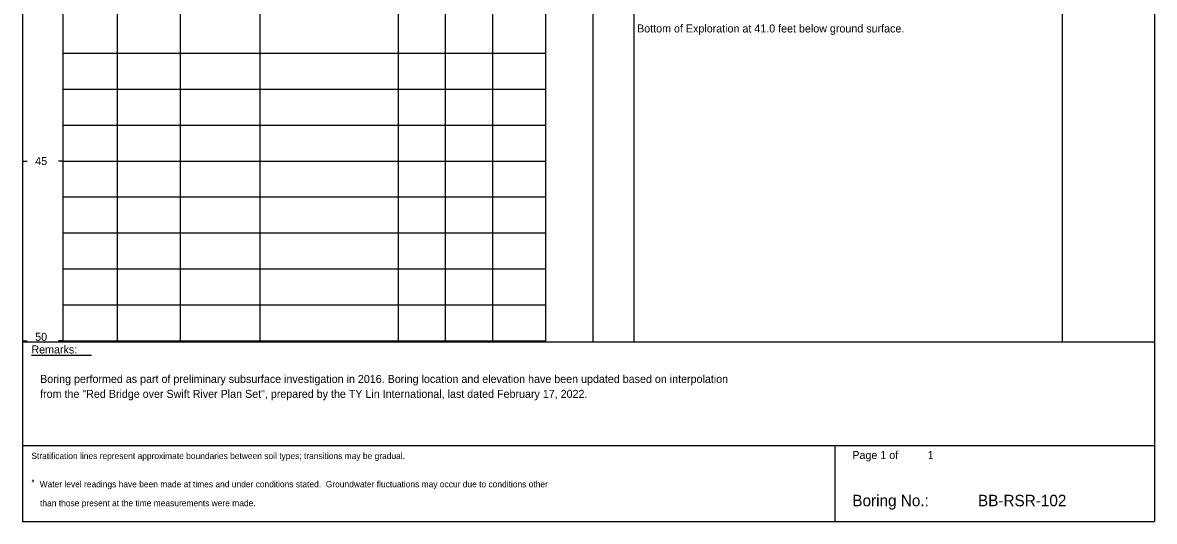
# Model space of a CAD drawing. Extents: x 9422 to 9552, y 6780 to 6860.
# Drawn here: x 9460.28 to 9491.78, y 6791.99 to 6805.86 of the extents above; entities that cross this region are included whole.
import ezdxf

# ---------------------------------------------------------------- set-up
doc = ezdxf.new("R2010")
doc.units = 0
doc.layers.add('7', color=7, linetype='Continuous')

msp = doc.modelspace()

# ---------------------------------------------------------------- linework, layer by layer
at = {"layer": '7'}
msp.add_line((9460.526, 6796.614), (9462.203, 6796.614), dxfattribs=at)
for points in [[(9460.282, 6822.038), (9460.282, 6791.992)], [(9461.4, 6822.038), (9461.4, 6796.983)], [(9462.909, 6822.038), (9462.909, 6796.983)], [(9464.665, 6822.038), (9464.665, 6796.983)], [(9466.879, 6822.038), (9466.879, 6796.983)], [(9470.734, 6822.038), (9470.734, 6796.983)], [(9472.046, 6822.038), (9472.046, 6796.983)], [(9473.359, 6822.038), (9473.359, 6796.983)], [(9474.835, 6822.038), (9474.835, 6796.983)], [(9476.148, 6822.038), (9476.148, 6796.983)], [(9477.296, 6822.038), (9477.296, 6796.983)], [(9489.214, 6822.038), (9489.214, 6796.983)], [(9491.778, 6822.038), (9491.778, 6791.992)], [(9461.4, 6805.011), (9462.909, 6805.011)], [(9462.909, 6805.011), (9464.665, 6805.011)], [(9464.665, 6805.011), (9466.879, 6805.011)], [(9466.879, 6805.011), (9470.734, 6805.011)], [(9470.734, 6805.011), (9472.046, 6805.011)], [(9472.046, 6805.011), (9473.359, 6805.011)], [(9473.359, 6805.011), (9474.835, 6805.011)], [(9461.4, 6804.011), (9462.909, 6804.011)], [(9462.909, 6804.011), (9464.665, 6804.011)], [(9464.665, 6804.011), (9466.879, 6804.011)], [(9466.879, 6804.011), (9470.734, 6804.011)], [(9470.734, 6804.011), (9472.046, 6804.011)], [(9472.046, 6804.011), (9473.359, 6804.011)], [(9473.359, 6804.011), (9474.835, 6804.011)], [(9461.4, 6803.011), (9462.909, 6803.011)], [(9462.909, 6803.011), (9464.665, 6803.011)], [(9464.665, 6803.011), (9466.879, 6803.011)], [(9466.879, 6803.011), (9470.734, 6803.011)], [(9470.734, 6803.011), (9472.046, 6803.011)], [(9472.046, 6803.011), (9473.359, 6803.011)], [(9473.359, 6803.011), (9474.835, 6803.011)], [(9460.282, 6802.011), (9460.404, 6802.011)], [(9461.4, 6802.011), (9461.279, 6802.011)], [(9461.4, 6802.011), (9462.909, 6802.011)], [(9462.909, 6802.011), (9464.665, 6802.011)], [(9464.665, 6802.011), (9466.879, 6802.011)], [(9466.879, 6802.011), (9470.734, 6802.011)], [(9470.734, 6802.011), (9472.046, 6802.011)], [(9472.046, 6802.011), (9473.359, 6802.011)], [(9473.359, 6802.011), (9474.835, 6802.011)], [(9461.4, 6801.011), (9462.909, 6801.011)], [(9462.909, 6801.011), (9464.665, 6801.011)], [(9464.665, 6801.011), (9466.879, 6801.011)], [(9466.879, 6801.011), (9470.734, 6801.011)], [(9470.734, 6801.011), (9472.046, 6801.011)], [(9472.046, 6801.011), (9473.359, 6801.011)], [(9473.359, 6801.011), (9474.835, 6801.011)], [(9461.4, 6800.011), (9462.909, 6800.011)], [(9462.909, 6800.011), (9464.665, 6800.011)], [(9464.665, 6800.011), (9466.879, 6800.011)], [(9466.879, 6800.011), (9470.734, 6800.011)], [(9470.734, 6800.011), (9472.046, 6800.011)], [(9472.046, 6800.011), (9473.359, 6800.011)], [(9473.359, 6800.011), (9474.835, 6800.011)], [(9461.4, 6799.011), (9462.909, 6799.011)], [(9462.909, 6799.011), (9464.665, 6799.011)], [(9464.665, 6799.011), (9466.879, 6799.011)], [(9466.879, 6799.011), (9470.734, 6799.011)], [(9470.734, 6799.011), (9472.046, 6799.011)], [(9472.046, 6799.011), (9473.359, 6799.011)], [(9473.359, 6799.011), (9474.835, 6799.011)], [(9461.4, 6798.011), (9462.909, 6798.011)], [(9462.909, 6798.011), (9464.665, 6798.011)], [(9464.665, 6798.011), (9466.879, 6798.011)], [(9466.879, 6798.011), (9470.734, 6798.011)], [(9470.734, 6798.011), (9472.046, 6798.011)], [(9472.046, 6798.011), (9473.359, 6798.011)], [(9473.359, 6798.011), (9474.835, 6798.011)], [(9460.282, 6797.011), (9460.404, 6797.011)], [(9460.282, 6796.983), (9491.778, 6796.983)], [(9461.4, 6797.011), (9461.279, 6797.011)], [(9461.4, 6797.011), (9462.909, 6797.011)], [(9462.909, 6797.011), (9464.665, 6797.011)], [(9464.665, 6797.011), (9466.879, 6797.011)], [(9466.879, 6797.011), (9470.734, 6797.011)], [(9470.734, 6797.011), (9472.046, 6797.011)], [(9472.046, 6797.011), (9473.359, 6797.011)], [(9473.359, 6797.011), (9474.835, 6797.011)], [(9460.282, 6794.1), (9491.778, 6794.1)], [(9482.887, 6794.1), (9482.887, 6791.992)], [(9460.282, 6791.992), (9491.778, 6791.992)]]:
    msp.add_lwpolyline(points, dxfattribs=at)

# ---------------------------------------------------------------- texts
for s, height, p in [('Bottom of Exploration at 41.0 feet below ground surface.', 0.2228, (9477.383, 6805.585)), ('45', 0.2228, (9460.632, 6801.899)), ('50', 0.2228, (9460.632, 6797.011)), ('Remarks:', 0.2228, (9460.526, 6796.66)), ('Boring performed as part of preliminary subsurface investigation in 2016. Boring location and elevation have been updated based on interpolation', 0.222801, (9460.769, 6795.84)), ('from the "Red Bridge over Swift River Plan Set", prepared by the TY Lin International, last dated February 17, 2022.', 0.222801, (9460.769, 6795.425)), ('Stratification lines represent approximate boundaries between soil types; transitions may be gradual.', 0.175058, (9460.526, 6793.724)), ('Page 1 of ', 0.2228, (9483.373, 6793.724)), ('1', 0.223, (9485.47, 6793.724)), ('*', 0.175, (9460.525, 6792.987)), (' Water level readings have been made at times and under conditions stated.  Groundwater fluctuations may occur due to conditions other', 0.175058, (9460.69, 6792.938)), ('Boring No.:', 0.31829, (9483.373, 6792.412)), ('than those present at the time measurements were made.', 0.17506, (9460.768, 6792.412)), ('BB-RSR-102', 0.3183, (9486.87, 6792.412))]:
    msp.add_text(s, height=height, dxfattribs=at).set_placement(p)

doc.saveas('drawing.dxf')
